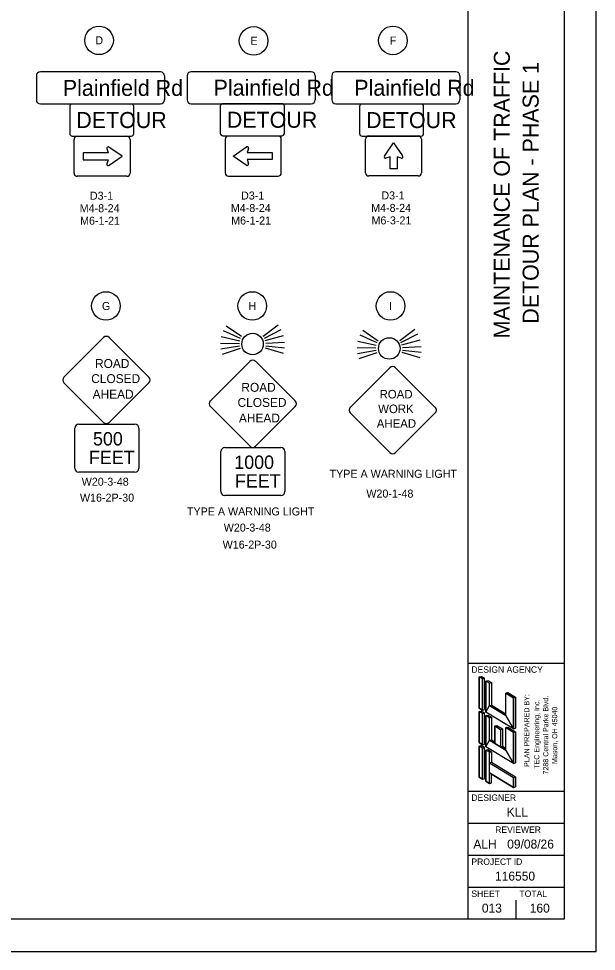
# Model space of a CAD drawing. Extents: x 0 to 42, y 0 to 22.
# Drawn here: x 24.96 to 33.98, y -0.05 to 14.52 of the extents above; entities that cross this region are included whole.
import ezdxf

# ---------------------------------------------------------------- set-up
doc = ezdxf.new("R2010")
doc.units = 0
for name, color, linetype in [('Default', 7, 'Continuous'), ('SH_Border', 7, 'Continuous'), ('SH_Cut_Line', 7, 'Continuous'), ('SH_Data', 7, 'Continuous'), ('SH_Text', 7, 'Continuous'), ('SN_P_Signs', 7, 'Continuous'), ('SN_P_Text', 7, 'Continuous')]:
    doc.layers.add(name, color=color, linetype=linetype)

msp = doc.modelspace()

# ---------------------------------------------------------------- linework, layer by layer
at = {"layer": 'SH_Border'}
for p, q in [((31.977, 0.455), (31.977, 21.455)), ((31.977, 4.455), (33.477, 4.455)), ((31.977, 2.455), (33.477, 2.455)), ((31.977, 1.955), (33.477, 1.955)), ((31.977, 1.455), (33.477, 1.455)), ((31.977, 0.955), (33.477, 0.955))]:
    msp.add_line(p, q, dxfattribs=at)
msp.add_lwpolyline([(1.477, 21.455), (33.477, 21.455), (33.477, 0.455), (1.477, 0.455)], close=True, dxfattribs=at)
at = {"layer": 'SH_Cut_Line'}
msp.add_lwpolyline([(-0.023, -0.045), (33.977, -0.045), (33.977, 21.955), (-0.023, 21.955)], close=True, dxfattribs=at)
at = {"layer": 'SH_Data'}
for p, q in [((32.727, 3.455), (32.727, 3.455)), ((32.727, 0.455), (32.727, 0.755)), ((32.352, 0.63), (32.352, 0.63))]:
    msp.add_line(p, q, dxfattribs=at)
at = {"layer": 'SH_Text'}
for p, q in [((32.146, 4.24), (32.178, 4.248)), ((32.146, 3.754), (32.146, 4.24)), ((32.2, 4.208), (32.146, 4.24)), ((32.232, 4.216), (32.178, 4.248)), ((32.2, 4.208), (32.232, 4.216)), ((32.2, 3.722), (32.2, 4.208)), ((32.232, 3.73), (32.232, 4.216)), ((32.254, 4.176), (32.286, 4.184)), ((32.308, 4.143), (32.254, 4.176)), ((32.254, 3.69), (32.254, 4.176)), ((32.286, 4.184), (32.34, 4.151)), ((32.308, 4.143), (32.34, 4.151)), ((32.308, 3.792), (32.308, 4.143)), ((32.34, 4.151), (32.34, 3.8)), ((32.564, 3.989), (32.597, 3.997)), ((32.564, 3.638), (32.564, 3.989)), ((32.686, 3.916), (32.564, 3.989)), ((32.597, 3.997), (32.718, 3.924)), ((32.308, 3.792), (32.34, 3.8)), ((32.564, 3.638), (32.308, 3.792)), ((32.34, 3.8), (32.564, 3.666)), ((32.686, 3.916), (32.718, 3.924)), ((32.686, 3.43), (32.686, 3.916)), ((32.718, 3.924), (32.718, 3.438)), ((32.2, 3.722), (32.146, 3.754)), ((32.146, 3.7), (32.178, 3.708)), ((32.146, 3.214), (32.146, 3.7)), ((32.2, 3.668), (32.146, 3.7)), ((32.232, 3.677), (32.178, 3.708)), ((32.2, 3.722), (32.232, 3.73)), ((32.2, 3.668), (32.232, 3.677)), ((32.2, 3.182), (32.2, 3.668)), ((32.232, 3.191), (32.232, 3.677)), ((32.686, 3.43), (32.254, 3.69)), ((32.254, 3.636), (32.286, 3.644)), ((32.286, 3.644), (32.34, 3.611)), ((32.254, 3.15), (32.254, 3.636)), ((32.308, 3.603), (32.254, 3.636)), ((32.308, 3.603), (32.34, 3.611)), ((32.308, 3.252), (32.308, 3.603)), ((32.34, 3.611), (32.34, 3.26)), ((32.392, 3.474), (32.425, 3.482)), ((32.392, 3.474), (32.392, 3.202)), ((32.392, 3.474), (32.48, 3.421)), ((32.425, 3.482), (32.512, 3.429)), ((32.48, 3.421), (32.512, 3.429)), ((32.48, 3.421), (32.48, 3.149)), ((32.512, 3.429), (32.512, 3.157)), ((32.564, 3.449), (32.597, 3.457)), ((32.564, 3.098), (32.564, 3.449)), ((32.686, 3.376), (32.564, 3.449)), ((32.597, 3.457), (32.718, 3.384)), ((32.686, 3.43), (32.718, 3.438)), ((32.686, 3.376), (32.718, 3.384)), ((32.686, 2.89), (32.686, 3.376)), ((32.718, 3.384), (32.718, 2.898)), ((32.2, 3.182), (32.146, 3.214)), ((32.308, 3.252), (32.34, 3.26)), ((32.392, 3.202), (32.308, 3.252)), ((32.34, 3.26), (32.392, 3.229)), ((32.146, 3.16), (32.178, 3.17)), ((32.146, 2.674), (32.146, 3.16)), ((32.2, 3.128), (32.146, 3.16)), ((32.232, 3.136), (32.178, 3.17)), ((32.199, 3.128), (32.232, 3.136)), ((32.2, 3.182), (32.232, 3.191)), ((32.2, 2.642), (32.2, 3.128)), ((32.232, 2.65), (32.232, 3.136)), ((32.686, 2.89), (32.254, 3.15)), ((32.254, 3.096), (32.286, 3.106)), ((32.308, 3.063), (32.254, 3.096)), ((32.254, 2.61), (32.254, 3.096)), ((32.286, 3.106), (32.34, 3.071)), ((32.308, 3.063), (32.34, 3.071)), ((32.308, 2.899), (32.308, 3.063)), ((32.34, 3.071), (32.34, 2.907)), ((32.48, 3.149), (32.512, 3.157)), ((32.564, 3.098), (32.48, 3.149)), ((32.512, 3.157), (32.564, 3.126)), ((32.308, 2.899), (32.34, 2.907)), ((32.308, 2.899), (32.686, 2.672)), ((32.34, 2.907), (32.718, 2.68)), ((32.686, 2.89), (32.718, 2.898)), ((32.2, 2.642), (32.146, 2.674)), ((32.2, 2.642), (32.232, 2.65)), ((32.308, 2.741), (32.686, 2.515)), ((32.308, 2.577), (32.308, 2.741)), ((32.34, 2.585), (32.34, 2.722)), ((32.686, 2.672), (32.718, 2.68)), ((32.686, 2.515), (32.686, 2.672)), ((32.718, 2.68), (32.718, 2.523)), ((32.308, 2.577), (32.254, 2.61)), ((32.308, 2.577), (32.34, 2.585)), ((32.686, 2.515), (32.718, 2.523))]:
    msp.add_line(p, q, dxfattribs=at)
for points in [[(32.146, 3.754), (32.2, 3.722), (32.2, 4.208), (32.146, 4.24)], [(32.254, 3.69), (32.308, 3.792), (32.308, 4.143), (32.254, 4.176)], [(32.686, 3.43), (32.564, 3.638), (32.564, 3.989), (32.686, 3.916)], [(32.254, 3.69), (32.308, 3.792), (32.564, 3.638), (32.686, 3.43)], [(32.146, 3.214), (32.2, 3.182), (32.2, 3.668), (32.146, 3.7)], [(32.254, 3.15), (32.308, 3.252), (32.308, 3.603), (32.254, 3.636)], [(32.392, 3.202), (32.392, 3.474), (32.48, 3.421), (32.48, 3.149)], [(32.686, 2.89), (32.564, 3.098), (32.564, 3.449), (32.686, 3.376)], [(32.254, 3.15), (32.308, 3.252), (32.564, 3.098), (32.686, 2.89)], [(32.146, 2.674), (32.2, 2.642), (32.2, 3.128), (32.146, 3.16)], [(32.254, 2.61), (32.308, 2.577), (32.308, 3.063), (32.254, 3.096)], [(32.308, 2.741), (32.308, 2.899), (32.686, 2.672), (32.686, 2.515)]]:
    msp.add_lwpolyline(points, close=True, dxfattribs=at)
for centre in [(26.216, 14.181), (28.628, 14.173), (30.802, 14.179), (26.323, 10.033), (28.607, 10.033), (30.765, 10.033)]:
    msp.add_circle(centre, 0.223, dxfattribs=at)
at = {"layer": 'SN_P_Signs'}
for p, q in [((25.876, 12.683), (26.651, 12.683)), ((29.01, 12.687), (28.235, 12.687)), ((29.01, 12.687), (29.01, 12.687)), ((30.424, 12.688), (31.199, 12.688)), ((25.826, 12.108), (25.826, 12.633)), ((26.701, 12.633), (26.701, 12.108)), ((28.185, 12.637), (28.185, 12.112)), ((29.06, 12.112), (29.06, 12.637)), ((30.374, 12.113), (30.374, 12.638)), ((30.67, 12.372), (30.812, 12.579)), ((30.812, 12.579), (30.952, 12.375)), ((31.249, 12.638), (31.249, 12.113)), ((26.358, 12.426), (25.967, 12.426)), ((25.967, 12.426), (25.967, 12.316)), ((26.338, 12.49), (26.358, 12.426)), ((26.576, 12.371), (26.37, 12.513)), ((28.31, 12.374), (28.517, 12.516)), ((28.548, 12.493), (28.528, 12.429)), ((28.528, 12.429), (28.919, 12.429)), ((28.919, 12.429), (28.919, 12.319)), ((25.967, 12.316), (26.358, 12.316)), ((26.358, 12.316), (26.338, 12.252)), ((26.372, 12.231), (26.576, 12.371)), ((28.514, 12.234), (28.31, 12.374)), ((28.919, 12.319), (28.528, 12.319)), ((28.528, 12.319), (28.548, 12.255)), ((30.757, 12.36), (30.693, 12.34)), ((30.757, 12.172), (30.757, 12.36)), ((30.931, 12.34), (30.867, 12.36)), ((30.867, 12.36), (30.867, 12.172)), ((30.867, 12.172), (30.757, 12.172)), ((26.651, 12.058), (25.876, 12.058)), ((28.235, 12.062), (29.01, 12.062)), ((31.199, 12.063), (30.424, 12.063))]:
    msp.add_line(p, q, dxfattribs=at)
for points in [[(29.528, 13.691), (27.653, 13.691)], [(25.238, 13.626), (25.238, 13.251)], [(27.175, 13.688), (25.3, 13.688)], [(27.238, 13.626), (27.238, 13.251)], [(27.59, 13.629), (27.59, 13.254)], [(29.59, 13.629), (29.59, 13.254)], [(29.849, 13.628), (29.849, 13.253)], [(31.786, 13.69), (29.911, 13.69)], [(31.849, 13.628), (31.849, 13.253)], [(25.3, 13.188), (27.175, 13.188)], [(25.759, 13.147), (25.759, 12.727)], [(26.719, 13.187), (25.799, 13.187)], [(26.759, 12.727), (26.759, 13.147)], [(27.653, 13.191), (29.528, 13.191)], [(28.108, 13.151), (28.108, 12.731)], [(29.068, 13.191), (28.148, 13.191)], [(29.108, 12.731), (29.108, 13.151)], [(29.911, 13.19), (31.786, 13.19)], [(30.282, 13.146), (30.282, 12.726)], [(31.242, 13.186), (30.322, 13.186)], [(31.282, 12.726), (31.282, 13.146)], [(25.799, 12.687), (26.719, 12.687)], [(28.148, 12.691), (29.068, 12.691)], [(30.322, 12.686), (31.242, 12.686)], [(25.669, 8.922), (26.288, 9.54)], [(26.376, 9.54), (26.995, 8.922)], [(27.953, 8.55), (28.572, 9.169)], [(28.66, 9.169), (29.279, 8.55)], [(30.137, 8.45), (30.755, 9.069)], [(30.844, 9.069), (31.463, 8.45)], [(26.288, 8.214), (25.669, 8.833)], [(26.995, 8.833), (26.376, 8.214)], [(28.572, 7.843), (27.953, 8.462)], [(29.279, 8.462), (28.66, 7.843)], [(30.755, 7.743), (30.137, 8.362)], [(31.463, 8.362), (30.844, 7.743)], [(25.901, 8.188), (26.776, 8.188)], [(25.838, 7.5), (25.838, 8.125)], [(26.838, 8.125), (26.838, 7.5)], [(28.117, 7.135), (28.117, 7.76)], [(28.18, 7.822), (29.055, 7.822)], [(29.117, 7.76), (29.117, 7.135)], [(26.776, 7.438), (25.901, 7.438)], [(29.055, 7.072), (28.18, 7.072)]]:
    msp.add_lwpolyline(points, dxfattribs=at)
for centre, radius, start, end in [((27.653, 13.629), 0.0625, 90, 180), ((29.528, 13.629), 0.0625, 0, 90), ((25.3, 13.626), 0.0625, 90, 180), ((27.175, 13.626), 0.0625, 0, 90), ((29.911, 13.628), 0.0625, 90, 180), ((31.786, 13.628), 0.0625, 0, 90), ((25.3, 13.251), 0.0625, 180, 270), ((25.799, 13.147), 0.04, 90, 180), ((26.719, 13.147), 0.04, 0, 90), ((27.175, 13.251), 0.0625, 270, 0), ((27.653, 13.254), 0.0625, 180, 270), ((28.148, 13.151), 0.04, 90, 180), ((29.068, 13.151), 0.04, 0, 90), ((29.528, 13.254), 0.0625, 270, 0), ((29.911, 13.253), 0.0625, 180, 270), ((30.322, 13.146), 0.04, 90, 180), ((31.242, 13.146), 0.04, 0, 90), ((31.786, 13.253), 0.0625, 270, 0), ((25.799, 12.727), 0.04, 180, 270), ((25.876, 12.633), 0.05, 90, 180), ((26.651, 12.633), 0.05, 0, 90), ((26.719, 12.727), 0.04, 270, 0), ((28.148, 12.731), 0.04, 180, 270), ((28.235, 12.637), 0.05, 90, 180), ((29.01, 12.637), 0.05, 0, 90), ((29.068, 12.731), 0.04, 270, 0), ((30.322, 12.726), 0.04, 180, 270), ((30.424, 12.638), 0.05, 90, 180), ((31.199, 12.638), 0.05, 0, 90), ((31.242, 12.726), 0.04, 270, 0), ((26.358, 12.496), 0.0209, 55.4112, 197.2046), ((28.528, 12.499), 0.0209, 342.7954, 124.5888), ((26.358, 12.246), 0.0209, 162.7954, 315.0096), ((28.528, 12.249), 0.0209, 224.9904, 17.2046), ((30.687, 12.36), 0.0209, 145.4112, 287.2046), ((30.937, 12.36), 0.0209, 252.7954, 45.0096), ((25.876, 12.108), 0.05, 180, 270), ((26.651, 12.108), 0.05, 270, 360), ((28.235, 12.112), 0.05, 180, 270), ((29.01, 12.112), 0.05, 270, 0), ((30.424, 12.113), 0.05, 180, 270), ((31.199, 12.113), 0.05, 270, 0), ((26.332, 9.496), 0.0625, 45, 135), ((28.616, 9.124), 0.0625, 45, 135), ((30.8, 9.024), 0.0625, 45, 135), ((25.713, 8.877), 0.0625, 135, 225), ((26.951, 8.877), 0.0625, 315, 45), ((27.997, 8.506), 0.0625, 135, 225), ((29.235, 8.506), 0.0625, 315, 45), ((30.181, 8.406), 0.0625, 135, 225), ((31.418, 8.406), 0.0625, 315, 45), ((25.901, 8.125), 0.0625, 90, 180), ((26.332, 8.259), 0.0625, 225, 315), ((26.776, 8.125), 0.0625, 0, 90), ((28.18, 7.76), 0.0625, 90, 180), ((28.616, 7.887), 0.0625, 225, 315), ((29.055, 7.76), 0.0625, 0, 90), ((30.8, 7.787), 0.0625, 225, 315), ((25.901, 7.5), 0.0625, 180, 270), ((26.776, 7.5), 0.0625, 270, 0), ((28.18, 7.135), 0.0625, 180, 270), ((29.055, 7.135), 0.0625, 270, 0)]:
    msp.add_arc(centre, radius, start, end, dxfattribs=at)
at = {"layer": 'SN_P_Text'}
for p, q in [((28.424, 9.524), (28.157, 9.647)), ((28.441, 9.554), (28.198, 9.72)), ((28.777, 9.562), (29.013, 9.738)), ((28.796, 9.532), (29.058, 9.667)), ((30.574, 9.486), (30.331, 9.652)), ((30.91, 9.493), (31.146, 9.67)), ((28.411, 9.484), (28.123, 9.549)), ((28.811, 9.493), (29.095, 9.57)), ((28.818, 9.451), (29.112, 9.47)), ((30.543, 9.415), (30.256, 9.48)), ((30.557, 9.456), (30.289, 9.579)), ((30.928, 9.464), (31.19, 9.599)), ((30.944, 9.424), (31.228, 9.502)), ((28.406, 9.442), (28.111, 9.448)), ((28.408, 9.404), (28.118, 9.356)), ((28.417, 9.371), (28.139, 9.274)), ((28.81, 9.379), (29.092, 9.295)), ((28.817, 9.413), (29.109, 9.378)), ((30.538, 9.374), (30.244, 9.38)), ((30.541, 9.336), (30.251, 9.288)), ((30.95, 9.345), (31.242, 9.31)), ((30.951, 9.383), (31.245, 9.402)), ((30.549, 9.302), (30.271, 9.206)), ((30.943, 9.311), (31.225, 9.227))]:
    msp.add_line(p, q, dxfattribs=at)
for centre in [(28.612, 9.438), (30.745, 9.37)]:
    msp.add_circle(centre, 0.168, dxfattribs=at)

# ---------------------------------------------------------------- texts
at = {"layer": 'Default'}
for s, p in [('PLAN PREPARED BY:', (32.931, 2.835)), ('TEC Engineering, Inc.', (33.087, 2.806)), ('7288 Central Parke Blvd.', (33.227, 2.717)), ('Mason, OH 45040', (33.367, 2.88))]:
    msp.add_text(s, height=0.08, rotation=90, dxfattribs=at).set_placement(p)
at = {"layer": 'SH_Data'}
for s, p in [('MAINTENANCE OF TRAFFIC', (32.627, 9.527)), ('DETOUR PLAN - PHASE 1', (33.077, 9.756))]:
    msp.add_text(s, height=0.25, rotation=90, dxfattribs=at).set_placement(p)
for s, height, p in [('DESIGN AGENCY', 0.1, (32.027, 4.305)), ('DESIGNER', 0.1, (32.027, 2.305)), ('KLL', 0.14, (32.578, 2.06)), ('REVIEWER', 0.1, (32.399, 1.805)), ('ALH', 0.14, (32.058, 1.56)), ('09/08/26', 0.14, (32.586, 1.56)), ('PROJECT ID', 0.1, (32.027, 1.305)), ('116550', 0.14, (32.396, 1.06)), ('SHEET', 0.1, (32.027, 0.805)), ('TOTAL', 0.1, (32.777, 0.805)), ('013', 0.14, (32.191, 0.56)), ('160', 0.14, (32.938, 0.56))]:
    msp.add_text(s, height=height, dxfattribs=at).set_placement(p)
at = {"layer": 'SH_Text'}
for s, p in [('D', (26.158, 14.119)), ('E', (28.579, 14.111)), ('F', (30.754, 14.116)), ('G', (26.261, 9.97)), ('H', (28.546, 9.97)), ('I', (30.74, 9.97))]:
    msp.add_text(s, height=0.125, dxfattribs=at).set_placement(p)
at = {"layer": 'SN_P_Signs'}
for s, height, p in [('     Plainfield Rd', 0.25, (25.186, 13.313)), ('     Plainfield Rd', 0.25, (27.539, 13.316)), ('    Plainfield Rd', 0.25, (29.828, 13.315)), ('DETOUR', 0.25, (25.861, 12.812)), ('DETOUR', 0.25, (28.21, 12.816)), ('DETOUR', 0.25, (30.384, 12.811)), ('ROAD', 0.1389, (26.153, 9.065)), ('CLOSED', 0.1389, (26.094, 8.829)), ('ROAD', 0.1389, (28.437, 8.693)), ('AHEAD', 0.1389, (26.116, 8.586)), ('CLOSED', 0.1389, (28.378, 8.457)), ('ROAD', 0.1333, (30.594, 8.589)), ('WORK', 0.1333, (30.572, 8.36)), ('AHEAD', 0.1389, (28.399, 8.214)), ('AHEAD', 0.1333, (30.55, 8.131)), ('500', 0.2083, (26.122, 7.855)), ('FEET', 0.2083, (26.059, 7.563)), ('1000', 0.2083, (28.327, 7.489)), ('FEET', 0.2083, (28.338, 7.197))]:
    msp.add_text(s, height=height, dxfattribs=at).set_placement(p)
at = {"layer": 'SN_P_Text'}
for s, p in [('D3-1', (26.073, 11.692)), ('D3-1', (28.432, 11.695)), ('D3-1', (30.622, 11.697)), ('M4-8-24', (25.914, 11.497)), ('M4-8-24', (28.273, 11.5)), ('M4-8-24', (30.463, 11.502)), ('M6-1-21', (25.92, 11.302)), ('M6-1-21', (28.278, 11.305)), ('M6-3-21', (30.468, 11.307)), ('TYPE A WARNING LIGHT', (29.814, 7.35)), ('W20-3-48', (25.945, 7.226)), ('W20-1-48', (30.388, 7.041)), ('W16-2P-30', (25.918, 6.977)), ('TYPE A WARNING LIGHT', (27.588, 6.762)), ('W20-3-48', (28.162, 6.51)), ('W16-2P-30', (28.145, 6.244))]:
    msp.add_text(s, height=0.125, dxfattribs=at).set_placement(p)

doc.saveas('drawing.dxf')
